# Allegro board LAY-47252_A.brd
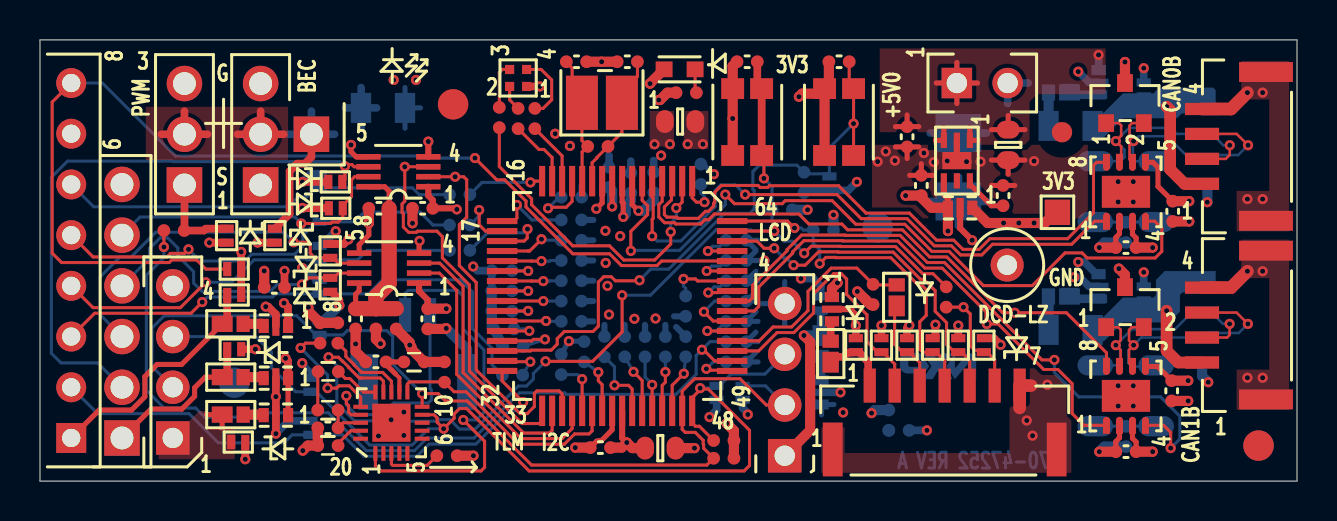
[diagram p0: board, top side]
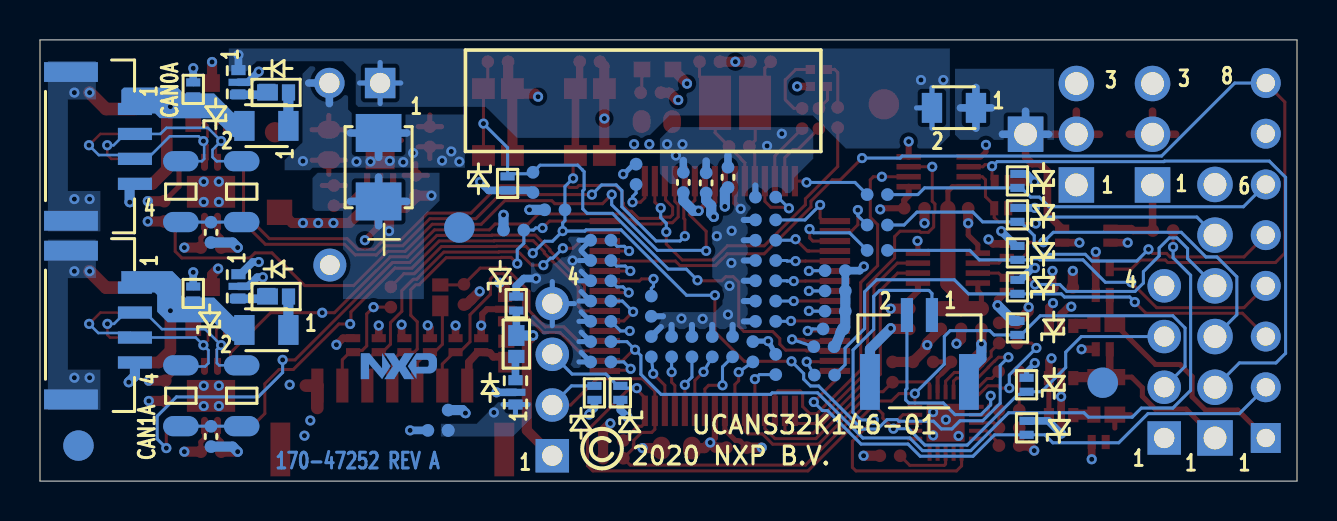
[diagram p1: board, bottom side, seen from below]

Outline 62.87 x 22.1 mm; copper layers: TOP, L2_GND, L3_PWR, BOTTOM. Coordinates in mm from the lower left corner of the outline.
Outline path: 0,22.1 0,0 62.87,0 62.87,22.1 0,22.1

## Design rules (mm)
constraint set DEFAULT: min track width 0.152
net group CAN0_: nets CAN0_H CAN0_L
net group CAN1_: nets CAN1_H CAN1_L
net group POWER: nets N03706 N08433 N08543 N11553 N17733 N16747780 N16805422 N16833767 N16895535 N16899617 N16939568

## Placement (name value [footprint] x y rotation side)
C1  10uF  [CC0603_OV]  32.02 18.01 180 top
C2  10uF  [CC0603_OV]  31.03 1.65 0 top
C3  0.1uF  [CC_FIL_0402]  39.09 4.45 90 bottom
C4  0.1UF  [CC0402_25]  30.7 14.96 90 bottom
C5  0.1UF  [CC0402_25]  29.55 14.94 270 bottom
C6  0.1UF  [CC0402_25]  28.46 15.21 270 bottom
C7  0.1UF  [CC0402_25]  28.03 1.68 180 top
C8  0.1uF  [CC_FIL_0402]  11.8 5.16 180 top
C9  0.1uF  [CC_FIL_0402]  52.95 19.98 270 bottom
C10  0.1uF  [CC_FIL_0402]  11.8 7.77 180 top
C11  0.1UF  [CC0402_25]  11.72 9.7 180 top
C12  4700pF  [CC0402_25]  54.32 2.24 270 bottom
C13  0.1UF  [CC0402_25]  54.32 1.47 180 top
C14  0.1UF  [CC0402_25]  56.6 4.52 270 top
C15  0.1uF  [CC_FIL_0402]  52.95 9.75 270 bottom
C17  0.033UF  [CC0402_25]  16.8 5.97 0 top
C24  0.1UF  [CC0402_25]  54.32 11.7 180 top
C25  0.1UF  [CC0402_25]  56.65 13.51 270 top
C26  4700pF  [CC0402_25]  54.32 12.46 270 bottom
C28  0.1uF  [CC_FIL_0402]  11.8 3.3 180 top
C30  0.033UF  [CC0402_25]  14.4 2.67 180 top
C32  0.1uF  [CC_FIL_0402]  39.61 8.61 270 top
C34  12PF  [CC0402_25]  29.37 21.01 180 top
C35  12PF  [CC0402_25]  26.83 21.01 0 top
C37  0.1UF  [CC0402_25]  19.14 13.67 0 top
C38  0.1UF  [CC0402_25]  16.95 13.67 0 top
C40  0.1UF  [CC0402_25]  43.37 17.25 270 top
C41  0.1UF  [CC0402_25]  44.08 14.81 90 top
C42  0.1UF  [CC0402_25]  39.97 21.01 180 top
C43  0.1uF  [CC_FIL_0402]  46.02 13.69 180 top
C44  0.1UF  [CC0402_25]  35.37 21.01 0 top
C66  0.1UF  [CC0402_25]  15.79 8.13 90 top
C67  0.1UF  [CC0402_25]  19.39 8.13 90 top
C68  470pF  [CC0402_25]  48.17 14.3 90 top
CP1  10uF  [CC0603_OV]  48.42 16.84 270 top
CP2  10uF  [CC3528-21]  45.94 15.72 90 bottom
D1  PMEG2020EPK  [DFN1608D-2]  9.54 3.33 0 top
D2  PESD5V0S1UL  [SOD-882]  9.72 9.32 0 top
D3  PESD5V0S1UL  [SOD-882]  13.98 7.67 90 bottom
D4  PESD5V0S1UL  [SOD-882]  13.53 4.82 90 bottom
D5  PESD5V0S1UL  [SOD-882]  9.92 1.96 0 top
D6  PMEG2020EPK  [DFN1608D-2]  51.07 19.47 180 bottom
D7  PESD5V0S1UL  [SOD-882]  13.53 2.67 90 bottom
D8  PMEG2020EPK  [DFN1608D-2]  51.07 9.25 180 bottom
D9  PESD1CAN  [SOT23_A]  54.27 8.71 0 top
D10  PESD5V0S1UL  [SOD-882]  55.21 19.62 90 bottom
D11  PESD5V0S1UL  [SOD-882]  9.72 6.6 0 top
D12  PESD5V0S1UL  [SOD-882]  14.77 14.99 180 top
D13  PESD5V0S1UL  [SOD-882]  14.52 11.53 90 top
D14  PESD5V0S1UL  [SOD-882]  14.52 9.83 270 top
D15  PESD5V0S1UL  [SOD-882]  14.8 13.67 180 top
D16  PMEG2020EPK  [DFN1608D-2]  9.54 5.21 0 top
D17  PESD5V0S1UL  [SOD-882]  40.8 6.81 90 top
D18  PESD5V0S1UL  [SOD-882]  42.09 6.81 90 top
D19  PESD5V0S1UL  [SOD-882]  43.37 6.81 90 top
D20  PESD5V0S1UL  [SOD-882]  44.65 6.81 90 top
D21  PESD5V0S1UL  [SOD-882]  45.93 6.81 90 top
D22  PESD5V0S1UL  [SOD-882]  47.21 6.81 90 top
D23  PMEG2020EPK  [DFN1608D-2]  42.85 9.2 90 top
D24  PESD5V0S1UL  [SOD-882]  55.21 9.4 90 bottom
D25  PESD5V0S1UL  [SOD-882]  9.33 12.29 270 top
D26  PESD5V0S1UL  [SOD-882]  11.75 12.29 270 top
D28  PESD5V0S1UL  [SOD-882]  13.98 9.73 90 bottom
D29  PMEG2020EPK  [DFN1608D-2]  39.55 6.38 90 top
D30  PESD5V0S1UL  [SOD-882]  13.98 11.43 90 bottom
D31  PESD5V0S1UL  [SOD-882]  13.98 13.34 90 bottom
D32  PESD5V0S1UL  [SOD-882]  13.98 15.04 90 bottom
D33  PESD5V0S1UL  [SOD-882]  9.72 10.62 0 top
D34  PMEG2020EPK  [DFN1608D-2]  39.05 6.87 270 bottom
D35  PMEG2020EPK  [DFN1608D-2]  9.54 7.87 0 top
D36  PESD5V0S1UL  [SOD-882]  39.48 14.91 270 bottom
D37  PESD5V0S1UL  [SOD-882]  35.14 4.42 270 bottom
D38  PESD5V0S1UL  [SOD-882]  33.85 4.42 270 bottom
D43  PESD5V0S1UL  [SOD-882]  39.05 8.89 90 bottom
D47  PESD1CAN  [SOT23_A]  54.27 18.94 0 top
F1  0ZCK0020FF2G  [FUSE_2P2X1P5]  51.55 7.57 0 bottom
F2  0ZCK0020FF2G  [FUSE_2P2X1P5]  51.55 17.79 0 bottom
F3  0ZCK0020FF2G  [FUSE_2P2X1P5]  17.16 18.69 0 bottom
IC1  S32K146  [LQFP64]  28.87 9.27 270 top
IC2  TJA1044GTK/3Z  [SON8_0P65_3P15X3P15]  54.32 4.27 90 top
IC3  SE050C1HQ1/Z01SCZ  [QFN20_0P4_3X3_TAB_1P9]  17.58 2.92 90 top
IC4  TJA1044GTK/3Z  [SON8_0P65_3P15X3P15]  54.32 14.49 90 top
IC5  74LVC2T45DC  [SSOP8_DCU]  17.92 15.49 90 top
IC7  MIC5219-3.3YML  [MLF6_TAB]  45.86 16.05 270 top
IC11  74LVC2T45DC  [SSOP8_DCU]  17.46 10.67 90 top
JP1  HDR 1X2  [HDR102]  45.86 19.94 90 top
L1  120 Ohm  [IND_0402]  18.71 5.97 180 top
L2  120 Ohm  [IND_0402]  14.41 5.49 0 top
L3  120 Ohm  [IND_0402]  14.4 3.56 180 top
L4  120 Ohm  [IND_0402]  14.4 1.78 0 top
LED1  RED/GRN/BLU  [LED4_0P85_1P25SQ_SMT]  23.91 20.19 270 top
LED5  BLUE  [LED_0603]  31.99 20.62 180 top
NOREF  -  []  50.44 9.25 0 top
NOREF#2  -  [unnamed#2]  20.66 18.87 0 top
NOREF#3  -  [unnamed#2]  60.95 1.78 0 top
NOREF#4  -  []  41.52 16.73 90 top
NOREF#5  -  []  10.36 7.45 90 top
NOREF#6  -  []  14.29 6.54 90 top
NOREF#7  -  []  12.06 12.18 90 top
NOREF#8  -  []  14.45 13.67 0 top
NOREF#9  -  []  14.29 12.21 90 top
NOREF#10  -  []  43.06 5.68 90 top
NOREF#11  -  []  51.27 0.48 90 top
NOREF#12  -  []  46.63 14.05 90 top
NOREF#13  -  []  39.24 16.31 90 top
NOREF#14  -  []  41.78 5.68 90 top
NOREF#15  -  []  44.65 6.46 90 top
NOREF#16  -  []  14.29 13.91 0 top
NOREF#17  -  []  61.32 13.04 90 top
NOREF#18  -  []  16.04 3.72 0 top
NOREF#19  -  []  14.29 10.3 90 top
NOREF#20  -  []  9.21 10.31 90 top
NOREF#21  -  []  43.06 5.68 0 top
NOREF#22  -  []  55.52 18.49 0 top
NOREF#23  -  []  15.04 16.01 0 top
NOREF#24  -  []  62.42 12.61 0 top
NOREF#25  -  []  9.21 9.01 0 top
NOREF#26  -  []  58.12 14.89 0 top
NOREF#27  -  []  33.54 4.31 0 top
NOREF#28  -  []  58.12 5.94 90 top
NOREF#29  -  []  8.71 7.45 0 top
NOREF#30  -  []  34.64 16.31 0 top
NOREF#31  -  []  62.87 0 90 top
NOREF#32  -  []  33.85 4.07 90 top
NOREF#33  -  []  39.09 3.84 90 top
NOREF#34  -  []  15.31 12.74 0 top
NOREF#35  -  []  12.41 5.51 90 top
NOREF#36  -  []  39.22 0.48 0 top
NOREF#37  -  []  9.21 6.29 90 top
NOREF#38  -  []  58.12 14.89 90 top
NOREF#39  -  []  45.62 5.68 90 top
NOREF#40  -  []  39.09 3.84 90 top
NOREF#41  -  []  45.93 6.46 90 top
NOREF#42  -  []  45.41 13.69 0 top
NOREF#43  -  []  10.36 4.78 90 top
NOREF#44  -  []  16.41 4.97 0 top
NOREF#45  -  []  13.84 1.54 90 top
NOREF#46  -  []  13.98 11.08 90 top
NOREF#47  -  []  8.71 2.9 0 top
NOREF#48  -  []  58.12 9.69 0 top
NOREF#49  -  []  39.05 8.54 90 top
NOREF#50  -  []  40.8 6.46 90 top
NOREF#51  -  []  39.65 1.58 0 top
NOREF#52  -  []  14.21 10.4 0 top
NOREF#53  -  []  58.12 18.64 0 top
NOREF#54  -  []  15.28 14.06 90 top
NOREF#55  -  []  39.05 6.24 90 top
NOREF#56  -  []  15.31 12.74 90 top
NOREF#57  -  []  22.15 1.4 90 top
NOREF#58  -  []  44.93 8.38 90 top
NOREF#59  -  []  11.19 7.77 0 top
NOREF#60  -  []  13.84 1.54 0 top
NOREF#61  -  []  9.11 7.87 0 top
NOREF#62  -  []  53.54 19.04 90 top
NOREF#63  -  []  14.42 14.99 0 top
NOREF#64  -  []  33.82 13.03 0 top
NOREF#65  -  []  9.21 9.01 90 top
NOREF#66  -  []  61.32 4.09 90 top
NOREF#67  -  []  11.8 5.16 0 top
NOREF#68  -  []  9.37 9.32 0 top
NOREF#69  -  []  41.78 5.68 0 top
NOREF#70  -  []  62.42 20.91 0 top
NOREF#71  -  []  9.57 1.96 0 top
NOREF#72  -  []  9.41 1.65 0 top
NOREF#73  -  []  41.5 4.78 0 top
NOREF#74  -  []  13.53 2.32 90 top
NOREF#75  -  []  14.29 6.54 0 top
NOREF#76  -  []  23.29 20.82 90 top
NOREF#77  -  []  12.41 8.13 90 top
NOREF#78  -  []  9.37 10.62 0 top
NOREF#79  -  []  55.52 8.27 0 top
NOREF#80  -  []  24.34 19.77 90 top
NOREF#81  -  []  39.65 1.58 0 top
NOREF#82  -  []  41.12 7.69 90 top
NOREF#83  -  []  39.61 8 90 top
NOREF#84  -  []  53.3 10.36 90 top
NOREF#85  -  []  58.12 14.89 90 top
NOREF#86  -  []  70.72 11.97 90 top
NOREF#87  -  []  12.06 12.18 0 top
NOREF#88  -  []  33.54 4.31 90 top
NOREF#89  -  []  27.58 3.84 90 top
NOREF#90  -  []  58.12 14.89 90 top
NOREF#91  -  []  52.95 19.37 90 top
NOREF#92  -  [unnamed#2]  51.12 17.48 0 top
NOREF#93  -  []  19.11 2.12 90 top
NOREF#94  -  []  14.83 9.72 0 top
NOREF#95  -  []  34.83 4.31 90 top
NOREF#96  -  []  35.14 4.07 90 top
NOREF#97  -  []  58.12 17.39 90 top
NOREF#98  -  []  41.5 4.78 0 top
NOREF#99  -  []  55.21 9.05 90 top
NOREF#100  -  []  39.36 7.76 0 top
NOREF#101  -  []  9.37 6.6 0 top
NOREF#102  -  []  42.87 6.56 0 top
NOREF#103  -  []  23.49 20.62 0 top
NOREF#104  -  []  11.75 11.94 90 top
NOREF#105  -  []  39.24 19.66 0 top
NOREF#106  -  []  39.26 9.22 90 top
NOREF#107  -  []  -390.36 -259.46 0 top
NOREF#108  -  []  23.81 20.76 0 top
NOREF#109  -  []  53.54 8.82 90 top
NOREF#110  -  []  9.21 6.29 0 top
NOREF#111  -  []  13.98 12.98 90 top
NOREF#112  -  []  38.73 3.84 90 top
NOREF#113  -  []  11.19 5.16 0 top
NOREF#114  -  []  11.19 3.3 0 top
NOREF#115  -  []  11.8 7.77 0 top
NOREF#116  -  []  39.48 14.56 90 top
NOREF#117  -  []  52.95 9.75 90 top
NOREF#118  -  []  46.9 5.68 0 top
NOREF#119  -  []  12.41 3.66 90 top
NOREF#120  -  []  58.12 8.44 90 top
NOREF#121  -  []  40.49 5.68 90 top
NOREF#122  -  []  39.36 7.76 90 top
NOREF#123  -  []  0.42 1.61 0 top
NOREF#124  -  []  9.64 12.18 0 top
NOREF#125  -  []  41.62 5.56 90 top
NOREF#126  -  []  14.29 10.3 0 top
NOREF#127  -  []  17.96 13.3 90 top
NOREF#128  -  []  70.72 12.61 90 top
NOREF#129  -  []  55.21 19.27 90 top
NOREF#130  -  []  58.12 18.64 90 top
NOREF#131  -  []  13.84 3.69 0 top
NOREF#132  -  []  15.28 14.06 0 top
NOREF#133  -  []  14.29 8.6 90 top
NOREF#134  -  []  58.12 5.94 0 top
NOREF#135  -  []  34.83 4.31 0 top
NOREF#136  -  []  70.72 3.67 90 top
NOREF#137  -  []  51.89 19.04 0 top
NOREF#138  -  []  21.78 3.84 0 top
NOREF#139  -  []  58.12 9.69 90 top
NOREF#140  -  []  46.02 13.69 0 top
NOREF#141  -  []  -44.79 -167.89 0 top
NOREF#142  -  []  34.62 5.52 90 top
NOREF#143  -  []  42.85 8.78 90 top
NOREF#144  -  []  9.11 5.21 0 top
NOREF#145  -  []  9.41 1.65 90 top
NOREF#146  -  []  61.32 4.09 90 top
NOREF#147  -  []  13.98 14.69 90 top
NOREF#148  -  []  14.52 11.18 90 top
NOREF#149  -  []  45.62 5.68 0 top
NOREF#150  -  []  -5.55 -35.31 0 top
NOREF#151  -  []  53.3 20.59 90 top
NOREF#152  -  []  0 0 0 top
NOREF#153  -  []  52.95 9.14 90 top
NOREF#154  -  []  39.79 15.42 90 top
NOREF#155  -  []  50.44 19.47 0 top
NOREF#156  -  []  44.34 5.68 90 top
NOREF#157  -  []  52.95 19.98 90 top
NOREF#158  -  []  18.26 8.32 0 top
NOREF#159  -  []  55.52 8.27 90 top
NOREF#160  -  []  39.97 5.56 0 top
NOREF#161  -  []  9.64 12.18 90 top
NOREF#162  -  []  13.53 4.47 90 top
NOREF#163  -  []  44.34 5.68 0 top
NOREF#164  -  []  47.21 6.46 90 top
NOREF#165  -  []  61.32 13.04 90 top
NOREF#166  -  []  43.37 6.46 90 top
NOREF#167  -  []  14.21 10.4 90 top
NOREF#168  -  []  58.12 5.94 90 top
NOREF#169  -  []  61.32 4.09 90 top
NOREF#170  -  []  46.82 5.11 90 top
NOREF#171  -  []  13.98 9.38 90 top
NOREF#172  -  []  11.8 3.3 0 top
NOREF#173  -  []  9.33 11.94 90 top
NOREF#174  -  []  49.75 11.74 0 top
NOREF#175  -  []  -363.69 261.62 0 top
NOREF#176  -  []  42.09 6.46 90 top
NOREF#177  -  []  13.98 7.32 90 top
NOREF#178  -  []  10.36 2.9 90 top
NOREF#179  -  []  43.28 8.38 0 top
NOREF#180  -  []  14.29 12.21 0 top
NOREF#181  -  []  13.84 3.69 90 top
NOREF#182  -  []  14.83 9.72 90 top
NOREF#183  -  []  62.42 11.97 0 top
NOREF#184  -  []  14.29 13.91 90 top
NOREF#185  -  []  33.82 13.03 90 top
NOREF#186  -  []  39.61 8.61 90 top
NOREF#187  -  []  62.42 3.67 0 top
NOREF#188  -  []  70.72 20.91 90 top
NOREF#189  -  []  41.52 16.73 0 top
NOREF#190  -  []  39.55 5.96 90 top
NOREF#191  -  []  51.89 8.82 0 top
NOREF#192  -  []  9.11 3.33 0 top
NOREF#193  -  []  46.9 5.68 90 top
NOREF#194  -  []  58.12 5.94 90 top
NOREF#195  -  []  40.49 5.68 0 top
NOREF#196  -  []  55.52 18.49 90 top
NOREF#197  -  []  23.29 22.07 0 top
NOREF#198  -  []  8.71 4.78 0 top
NOREF#199  -  []  9.21 10.31 0 top
NOREF#200  -  []  14.52 9.48 90 top
NOREF#201  -  []  36.09 16.31 90 top
NOREF#202  -  []  39.17 15.42 0 top
NOREF#203  -  []  39.47 7.69 0 top
NOREF#204  -  []  61.32 13.04 90 top
NOREF#205  -  []  14.29 8.6 0 top
NOREF#206  -  []  50.85 1.58 90 top
NOREF#207  -  []  34.76 1.6 180 bottom
NOREF#208  -  [unnamed#2]  60.95 1.78 180 bottom
NOREF#209  -  []  46.82 5.11 180 bottom
NOREF#210  -  [unnamed#2]  41.9 12.7 180 bottom
NOREF#211  -  [unnamed#2]  9.72 4.93 180 bottom
NOREF#212  -  []  23.81 21.59 0 bottom
P1  HDR 1X8  [HDR1X8_2P54_TH]  1.56 2.16 180 top
P2  HDR_1X6  [HDR106_B]  4.1 2.16 180 top
P3  HDR_1X4  [HDR104]  6.64 2.16 180 top
P4  HDR_1X4  [HDR104]  37.25 1.27 180 top
P5  CON_1X4  [CON_1X4_1P25_8P25X4P25_SM_RA]  60.37 7.82 270 bottom
P6  CON_1X7  [CON1X7_1P25_12X4P05_SM_RA]  45.25 2.53 0 top
P7  CON_1X4  [CON_1X4_1P25_8P25X4P25_SM_RA]  60.37 16.76 90 top
P8  CON_1X4  [CON_1X4_1P25_8P25X4P25_SM_RA]  60.37 16.76 270 bottom
P9  CON_1X4  [CON_1X4_1P25_8P25X4P25_SM_RA]  60.37 7.82 90 top
P10  CON 1X2  [CON_1X2_1P25_5P75X4P25_SM]  18.88 5.99 180 bottom
P11  HDR 1X3  [HDR103_A]  11.04 14.83 180 top
P12  HDR 1X3  [HDR103_A]  7.23 14.83 180 top
P13  HDR_1X1_TH  [HDR101_045T]  13.58 17.37 180 top
R1  49.9  [RC0402_25]  23.63 5.31 180 bottom
R2  49.9  [RC0402_25]  20.99 11.56 180 bottom
R3  60.4  [RC1206_OV]  55.83 14.5 270 bottom
R4  60.4  [RC1206_OV]  52.78 14.5 270 bottom
R5  3.3K  [RC0402_25]  20.36 1.27 180 top
R6  3.3K  [RC0402_25]  14.01 7.42 270 top
R7  49.9  [RC0402_25]  20.99 12.83 180 bottom
R8  10.0K  [RC0402_25]  41.67 9.35 90 top
R9  10.0K  [RC0402_25]  39.18 12.57 180 bottom
R10  1.0K  [RC0402_25]  45.33 9.22 270 top
R11  10.0K  [RC0402_25]  37.12 13.59 180 bottom
R12  49.9  [RC0402_25]  20.99 14.35 180 bottom
R13  1M  [RC0402_25]  27.9 16.76 180 top
R14  100K  [RC0402_25]  23.1 10.54 0 bottom
R15  100K  [RC0402_25]  26.58 10.03 180 bottom
R16  100K  [RC0402_25]  26.58 8 180 bottom
R17  100K  [RC0402_25]  23.2 7.62 0 bottom
R18  6.8K  [RC0402_25]  24.75 18.16 90 top
R19  6.8K  [RC0402_25]  23.91 18.16 90 top
R20  6.8K  [RC0402_25]  22.97 18.21 90 top
R21  100K  [RC0402_25]  23.66 6.73 0 bottom
R22  10.0K  [RC0402_25]  38.21 14.96 270 bottom
R23  60.4  [RC1206_OV]  52.78 4.27 270 bottom
R24  60.4  [RC1206_OV]  55.83 4.27 270 bottom
R25  100K  [RC0402_25]  32.3 8.76 90 bottom
R26  100K  [RC0402_25]  26.07 5.84 270 bottom
R27  3.3K  [RC0402_25]  14.9 7.42 270 top
R28  330  [RC0402_25]  6.71 12.55 0 top
R36  100K  [RC0402_25]  34.82 12.07 180 bottom
R39  3.3K  [RC0402_25]  34.2 2.03 180 top
R40  3.3K  [RC0402_25]  34.2 1.14 180 top
R41  0  [RC0402_25]  42.46 3.05 90 bottom
R42  0  [RC0402_25]  42.96 2.54 180 bottom
R43  3.3K  [RC0402_25]  20.23 5.46 270 top
R44  0  [RC0402_25]  16.8 8.13 90 top
R46  0  [RC0402_25]  17.82 8.13 270 top
R53  100K  [RC0402_25]  33.06 15.37 270 bottom
R55  100K  [RC0402_25]  26.58 14.22 180 bottom
R56  100K  [RC0402_25]  26.58 13.08 180 bottom
R57  100K  [RC0402_25]  26.58 12.07 180 bottom
R58  100K  [RC0402_25]  26.58 11.05 180 bottom
R59  100K  [RC0402_25]  23.1 9.52 0 bottom
R60  100K  [RC0402_25]  26.58 9.02 180 bottom
R61  100K  [RC0402_25]  23.1 8.51 0 bottom
R63  100K  [RC0402_25]  32.3 6.73 270 bottom
R64  100K  [RC0402_25]  31.28 6.73 270 bottom
R65  100K  [RC0402_25]  30.26 6.73 270 bottom
R66  100K  [RC0402_25]  29.25 6.73 270 bottom
R67  100K  [RC0402_25]  28.23 6.73 270 bottom
R68  100K  [RC0402_25]  27.22 6.48 270 bottom
R69  100K  [RC0402_25]  34.82 5.97 180 bottom
R70  100K  [RC0402_25]  34.82 6.98 180 bottom
R71  100K  [RC0402_25]  34.82 8 180 bottom
R72  100K  [RC0402_25]  34.82 9.02 180 bottom
R75  100K  [RC0402_25]  34.82 10.03 180 bottom
R76  100K  [RC0402_25]  34.82 11.05 180 bottom
R80  1.0K  [RC0402_25]  32.32 19.46 180 top
SW1  EVP-AA602W  [SW4_SPST_3P5X2P9_SM]  35.37 17.98 90 top
SW3  EVP-AA602W  [SW4_SPST_3P5X2P9_SM]  39.97 17.98 270 top
TP7  TP 50MILS SQ  [TESTPOINT_050_SQ]  50.89 13.46 0 top
TP8  TERMINAL ASSY  [TP_039_130MIL_TH]  48.37 10.82 0 top
Y1  8MHZ  [XTAL2_3P3X2P6]  28.1 18.95 180 top

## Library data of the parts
C1 C2 C4-C7 C11-C14 C17 C24-C26 C30 C34 C35 C37 C38 C40-C42 C44 C66-C68 CP1 = CAP_NP
C3 C8-C10 C15 C28 C32 C43 = EMIFILTER_NFM21P
CP2 = CAP_POL
D1 D6 D8 D16 D23 D29 D34 D35 = DIODE_SCHTKY
D2-D5 D7 D10-D15 D17-D22 D24-D26 D28 D30-D33 D36-D38 D43 = DIODE_TVS
D9 D47 = DIODE_BIDIR_3P
F1-F3 = FUSE_RESETTABLE
IC1 = S32K146_64P_ALT
IC2 IC4 = TJA1044GT3_HVSON8
IC3 = SE050TBD_HX2QFN20
IC5 IC11 = 74LVC2T45DC
IC7 = MIC5305_MLF_6P
JP1 = CONN_HDR_2X1
L1-L4 = INDUCTOR_FERRITE
LED1 = LED_TRI_SMLP34RGB1W3
LED5 = LED
P1 = CONN_HDR_8X1
P2 = CONN_HDR_6X1
P3 P4 = CONN_HDR_4X1
P5 P7-P9 = CONN_1x4_SHLD
P6 = CONN_1X7_SHLD
P10 = CONN_2X1_SH
P11 P12 = CONN_HDR_3X1
P13 = CONN_HDR_1X1
R1-R28 R36 R39-R44 R46 R53 R55-R61 R63-R72 R75 R76 R80 = RES
SW1 SW3 = SW4_LT_SPST_4P
TP7 = T POINT S
TP8 = TestLoop
Y1 = XTAL

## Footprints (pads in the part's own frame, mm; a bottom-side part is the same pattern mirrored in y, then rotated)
CC0402_25
  round 0.635 smd: 1(-0.508,0) 2(0.508,0)
CC0603_OV
  oval 0.889x1.143 smd: 1(-0.762,0) 2(0.762,0)
CC3528-21
  rect 1.905x2.286 smd: 1(-1.714,0) 2(1.714,0)
CC_FIL_0402
  rect 0.508x0.711 smd: 1(-0.61,0) 3(0.61,0)
  rect 0.356x0.991 smd: 2(0,0)
CON1X7_1P25_12X4P05_SM_RA
  rect 0.61x1.702 smd: 1(-3.75,2.25) 2(-2.5,2.25) 3(-1.25,2.25) 4(0,2.25) 5(1.25,2.25) 6(2.5,2.25) 7(3.75,2.25)
  rect 0.991x2.692 smd: SH1(-5.6,-0.95) SH2(5.6,-0.95)
CON_1X2_1P25_5P75X4P25_SM
  rect 0.61x1.702 smd: 1(0.625,2.322) 2(-0.625,2.322)
  rect 0.991x2.794 smd: S1(-2.475,-1.028) S2(2.475,-1.028)
CON_1X4_1P25_8P25X4P25_SM_RA
  rect 0.61x1.702 smd: 1(-1.875,2.247) 2(-0.625,2.247) 3(0.625,2.247) 4(1.875,2.247)
  rect 0.991x2.692 smd: SH1(-3.725,-0.953) SH2(3.725,-0.953)
DFN1608D-2
  rect 0.66x0.813 smd: A(0.625,0)
  rect 1.041x0.813 smd: C(-0.425,0)
FUSE_2P2X1P5
  rect 1.016x1.499 smd: 1(-1.1,0) 2(1.1,0)
HDR1X8_2P54_TH
  rect 1.499x1.499 hole 0.914: 1(0,0)
  round 1.499 hole 0.914: 2(0,-2.54) 3(0,-5.08) 4(0,-7.62) 5(0,-10.16) 6(0,-12.7) 7(0,-15.24) 8(0,-17.78)
HDR101_045T
  rect 1.778x1.778 hole 1.143: 1(0,0)
HDR102
  rect 1.524x1.524 hole 1.016: 1(0,0)
  round 1.524 hole 1.016: 2(0,-2.54)
HDR103_A
  rect 1.778x1.778 hole 1.143: 1(0,0)
  round 1.778 hole 1.143: 2(0,-2.54) 3(0,-5.08)
HDR104
  rect 1.676x1.676 hole 1.016: 1(0,0)
  round 1.676 hole 1.016: 2(0,-2.54) 3(0,-5.08) 4(0,-7.62)
HDR106_B
  rect 1.778x1.778 hole 1.143: 1(0,0)
  round 1.778 hole 1.143: 2(0,-2.54) 3(0,-5.08) 4(0,-7.62) 5(0,-10.16) 6(0,-12.7)
IND_0402
  round 0.635 smd: 1(-0.508,0) 2(0.508,0)
LED4_0P85_1P25SQ_SMT
  rect 0.457x0.457 smd: 1(0.425,0.425) 2(0.425,-0.425) 3(-0.425,-0.425) 4(-0.425,0.425)
LED_0603
  rect 0.838x0.787 smd: A(-0.775,0) C(0.775,0)
LQFP64
  rect 1.524x0.305 smd: 1(-5.753,3.753) 2(-5.753,3.252) 3(-5.753,2.752) 4(-5.753,2.252) 5(-5.753,1.751) 6(-5.753,1.251) 7(-5.753,0.751) 8(-5.753,0.25) 9(-5.753,-0.25) 10(-5.753,-0.751) 11(-5.753,-1.251) 12(-5.753,-1.751) 13(-5.753,-2.252) 14(-5.753,-2.752) 15(-5.753,-3.252) 16(-5.753,-3.753) 33(5.753,-3.753) 34(5.753,-3.252) 35(5.753,-2.752) 36(5.753,-2.252) 37(5.753,-1.751) 38(5.753,-1.251) 39(5.753,-0.751) 40(5.753,-0.25) 41(5.753,0.25) 42(5.753,0.751) 43(5.753,1.251) 44(5.753,1.751) 45(5.753,2.252) 46(5.753,2.752) 47(5.753,3.252) 48(5.753,3.753)
  rect 0.305x1.524 smd: 17(-3.753,-5.753) 18(-3.252,-5.753) 19(-2.752,-5.753) 20(-2.252,-5.753) 21(-1.751,-5.753) 22(-1.251,-5.753) 23(-0.751,-5.753) 24(-0.25,-5.753) 25(0.25,-5.753) 26(0.751,-5.753) 27(1.251,-5.753) 28(1.751,-5.753) 29(2.252,-5.753) 30(2.752,-5.753) 31(3.252,-5.753) 32(3.753,-5.753) 49(3.753,5.753) 50(3.252,5.753) 51(2.752,5.753) 52(2.252,5.753) 53(1.751,5.753) 54(1.251,5.753) 55(0.751,5.753) 56(0.25,5.753) 57(-0.25,5.753) 58(-0.751,5.753) 59(-1.251,5.753) 60(-1.751,5.753) 61(-2.252,5.753) 62(-2.752,5.753) 63(-3.252,5.753) 64(-3.753,5.753)
MLF6_TAB
  rect 0.762x0.305 smd: 1(-1.016,0.65) 2(-1.016,0) 3(-1.016,-0.65) 4(1.016,-0.65) 5(1.016,0) 6(1.016,0.65)
  rect 0.864x1.448 smd: 7(0,0)
QFN20_0P4_3X3_TAB_1P9
  rect 0.737x0.203 smd: 1(-1.538,0.8) 2(-1.538,0.4) 3(-1.538,0) 4(-1.538,-0.4) 5(-1.538,-0.8) 11(1.538,-0.8) 12(1.538,-0.4) 13(1.538,0) 14(1.538,0.4) 15(1.538,0.8)
  rect 0.203x0.737 smd: 6(-0.8,-1.538) 7(-0.4,-1.538) 8(0,-1.538) 9(0.4,-1.538) 10(0.8,-1.538) 16(0.8,1.538) 17(0.4,1.538) 18(0,1.538) 19(-0.4,1.538) 20(-0.8,1.538)
  rect 1.905x1.905 smd: 21(0,0)
RC0402_25
  round 0.635 smd: 1(-0.508,0) 2(0.508,0)
RC1206_OV
  oval 1.016x1.778 smd: 1(-1.524,0) 2(1.524,0)
SOD-882
  rect 0.406x0.711 smd: A(0.35,0) C(-0.35,0)
SON8_0P65_3P15X3P15
  custom 0.088x0.088 smd: 1(-1.475,0.975) 2(-1.475,0.325) 3(-1.475,-0.325) 4(-1.475,-0.975) 5(1.475,-0.975) 6(1.475,-0.325) 7(1.475,0.325) 8(1.475,0.975)
  rect 1.6x2.413 smd: 9(0,0)
SOT23_A
  rect 0.787x0.889 smd: 1(-0.94,-1.003) 2(0.94,-1.003) 3(0,1.003)
SSOP8_DCU
  rect 0.279x1.219 smd: 1(-0.75,-1.499) 2(-0.25,-1.499) 3(0.25,-1.499) 4(0.75,-1.499) 5(0.75,1.499) 6(0.25,1.499) 7(-0.25,1.499) 8(-0.75,1.499)
SW4_SPST_3P5X2P9_SM
  rect 1.041x1.143 smd: A1(-1.675,0.725) A2(1.675,0.725) B1(-1.675,-0.725) B2(1.675,-0.725)
TESTPOINT_050_SQ
  rect 1.27x1.27 smd: 1(0,0)
TP_039_130MIL_TH
  round 1.651 hole 0.991: 1(0,0)
unnamed#2
  round 1.524 smd: (0,0)
XTAL2_3P3X2P6
  rect 1.6x2.718 smd: 1(-1,0) 2(1,0)

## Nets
3V3: C1.1 C2.1 C4.1 C5.2 C6.2 C7.1 C14.1 C25.1 C32.1 C37.2 C42.2 C43.1 C67.2 IC1.7 IC1.8 IC1.9 IC1.41 IC2.5(VIO) IC4.5(VIO) IC5.1 IC5.5 IC11.1 L1.1 LED1.1 R5.1 R6.1 R8.1 R9.1 R11.1 R27.1 R39.1 R40.1 R42.1 R43.1 R46.2 R80.2 SW3.B1 SW3.B2 TP7.1(TP)
5V: C8.1 C9.1 C10.1 C11.1 C13.1 C15.1 C24.1 C28.1 C40.1 CP1.1 F3.2 IC2.3 IC4.3 IC7.1 IC7.3 JP1.1 R41.2 R44.1
GND: C1.2 C2.2 C3.2 C4.2 C5.1 C6.1 C7.2 C8.2 C9.2 C10.2 C11.2 C12.2 C13.2 C14.2 C15.2 C17.1 C24.2 C25.2 C26.2 C28.2 C30.2 C32.2 C34.2 C35.2 C37.1 C38.1 C40.2 C41.2 C43.2 C44.1 C66.1 C67.1 C68.2 CP1.2 CP2.2 D2.A D3.A D4.A D5.A D7.A D9.3(CC) D10.A D11.A D12.A D13.A D14.A D15.A D17.A D18.A D19.A D20.A D21.A D22.A D24.A D25.A D26.A D28.A D30.A D31.A D32.A D33.A D36.A D37.A D38.A D43.A D47.3(CC) IC1.10 IC1.40(VSS_2) IC2.2 IC2.9 IC3.21 IC4.2 IC4.9 IC5.4 IC7.2 IC7.7 IC11.4 IC11.5 JP1.2 L4.1 LED5.C(CATHODE) P1.7 P2.6 P3.4 P4.4 P5.4 P5.SH1 P5.SH2 P6.7 P6.SH1 P6.SH2 P7.4 P7.SH1 P7.SH2 P8.4 P8.SH1 P8.SH2 P9.4 P9.SH1 P9.SH2 P10.S1 P10.S2 P11.3 P12.3 R14.1 R15.1 R16.1 R17.1 R21.1 R22.2 R25.1 R26.1 R36.1 R53.1 R55.1 R56.1 R57.1 R58.1 R59.1 R60.1 R61.1 R63.1 R64.1 R65.1 R66.1 R67.1 R68.1 R69.1 R70.1 R71.1 R72.1 R75.1 R76.1 SW1.A1 SW1.A2 TP8.1(PIN1)
6-WR-SPI_CS_N: IC1.18 R7.1
6-WR-SPI_INT_N: IC1.16 R12.1
6-WR-SPI_MISO: IC1.31 R1.1
6-WR-SPI_MOSI: IC1.19 R2.1
6-WR-SPI_RDY_N: D33.C IC1.60 P1.8
6-WR-SPI_SCK: D7.C IC1.32 P1.2
CAN0_H: D47.1 IC4.7 P7.2 P8.2 R4.1
CAN0_L: D47.2 IC4.6 P7.3 P8.3 R3.1
CAN0_RX: IC1.6 IC4.4
CAN0_STB: IC1.3 IC4.8
CAN0_TX: IC1.5 IC4.1
CAN1_H: D9.1 IC2.7 P5.2 P9.2 R23.1
CAN1_L: D9.2 IC2.6 P5.3 P9.3 R24.1
CAN1_RX: IC1.56 IC2.4
CAN1_STB: IC1.4 IC2.8
CAN1_TX: IC1.55 IC2.1
CS_N: D31.C P1.5 R7.2
I2C_SCL: D3.C D37.C IC1.47 IC3.10 P3.2 P4.2 R40.2
I2C_SDA: D4.C D38.C IC1.48 IC3.9 P3.3 P4.3 R39.2
INT_N: D32.C P1.6 R12.2
LED1_BLUE: IC1.2 R20.1
LED1_GREEN: IC1.14 R18.1
LED1_RED: IC1.15 R19.1
LPUART0_CTS: IC1.36 IC11.2
LPUART0_RTS: IC1.35 IC5.2
LPUART0_RX: IC1.34 IC11.3
LPUART0_TX: IC1.33 IC5.3
LPUART1_RX: D23.A IC1.52 R8.2
LPUART1_TX: D18.C IC1.51 P6.2
MISO: D28.C P1.3 R1.2
MOSI: D30.C P1.4 R2.2
PTA0: IC1.50 R28.1 R70.2
PTA1: IC1.49 R69.2
PTA7: IC1.37 R26.2
PTA10: IC1.58 R25.2
PTA11: IC1.57 R75.2
PTB6: C35.1 IC1.12 R13.2 Y1.2
PTB7: C34.1 IC1.11 R13.1 Y1.1
PTB12: IC1.43 R66.2
PTB13: IC1.42 R67.2
PTC0: IC1.26 R61.2
PTC1: IC1.25 R60.2
PTC2: IC1.21 R58.2
PTC3: IC1.20 R57.2
PTC5: IC1.61 R36.2
PTC14: C42.1 D36.C IC1.30 R22.1 SW3.A1 SW3.A2
PTC15: IC1.29 R21.2
PTC16: IC1.28 R17.2
PTC17: IC1.27 R16.2
PTD1: IC1.1 R53.2
PTD2: IC1.46 R63.2
PTD3: IC1.45 R64.2
PTD4: IC1.44 R65.2
PTD5: IC1.24 R59.2
PTD6: IC1.23 R15.2
PTD7: IC1.22 R14.2
PTE1: IC1.59 R76.2
PTE2: IC1.54 R72.2
PTE3: IC1.13 R55.2
PTE6: IC1.53 R71.2
PTE7: IC1.39 R68.2
PTE8: IC1.17 R56.2
S32_RST_N: C44.2 IC1.63 IC3.14 R10.1 R11.2 SW1.B1 SW1.B2
S32_SWD_CLK: D21.C IC1.62 P6.5
S32_SWD_DIO: D20.C IC1.64 P6.4 R9.2
SE_ENA: IC1.38 IC3.11 R43.2
SE_LA: IC3.17 P10.2
SE_LB: IC3.1 P10.1
SE_SCL: IC3.16 R6.2
SE_SDA: IC3.3 R5.2
UART0_CTS: D14.C IC11.7 P2.4
UART0_RTS: D15.C IC5.7 P2.5
UART0_RX: D13.C IC11.6 P2.3
UART0_TX: D12.C IC5.6 P2.2
N00466: D19.C D23.C P6.3
N00470: D17.C D29.C P6.1
N00518: D22.C P6.6 R10.2
N02898: D10.C F2.2 P7.1 P8.1
N03706: D24.C F1.2 P5.1 P9.1
N08433: D2.C D35.C P1.1
N08543: C38.2 C66.2 IC5.8(VCCB) IC11.8(VCCB) R44.2 R46.1
N11553: D11.C D16.C P2.1
N16948: D1.C D5.C P3.1
N17733: D34.C D43.C P4.1
N18118: C3.1 R41.1 R42.2
N20024: C41.1 C43.3(OUTPUT) CP2.1 IC7.4(VOUT)
N21801: LED5.A R80.1
N42723: LED1.4(CATHODE3) R18.2
N16747780: C10.3(OUTPUT) D35.A
N16752305: C26.1 R3.2 R4.2
N16762980: C12.1 R23.2 R24.2
N16766876: C32.3(OUTPUT) D29.A
N16781617: LED1.3 R20.2
N16781620: LED1.2 R19.2
N16805422: C8.3(OUTPUT) D16.A
N16833767: C28.3(OUTPUT) D1.A
N16834186: C3.3(OUTPUT) D34.A
N16850472: C17.2 IC3.12 L1.2
N16850531: C30.1 IC3.18 L3.1
N16850565: IC3.15 L2.2
N16850567: L2.1 L3.2
N16850641: IC3.19(VSS) L4.2
N16885160: IC3.13 R27.2
N16895535: D8.A F1.1
N16895554: C15.3(OUTPUT) D8.C
N16899266: C9.3(OUTPUT) D6.C
N16899617: D6.A F2.1
N16901866: D26.C F3.1 P13.1
N16903080: D25.C P12.1 R28.2
N16904839: P11.2 P12.2
N16939568: C68.1 IC7.6

Pads without a net: IC3 2 4 5 6 7 8 20; IC7 5; P11 1

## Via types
v1: diameter 0.508, hole 0.254, TOP to BOTTOM, 226 vias

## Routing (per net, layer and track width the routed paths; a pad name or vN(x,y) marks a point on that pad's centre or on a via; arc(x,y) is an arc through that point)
3V3: length 49
  TOP w0.254: IC2.5 55.89,5.74 C14.1 ; IC1.8 29.12,13.97 29.17,13.92 v1(29.17,13.23) ; C25.1 55.92,14.76 55.92,15.71 55.66,15.97 IC4.5 ; v1(29.93,13.54) 29.62,13.85 IC1.7 ; v1(15.56,16.84) 15.56,16.5 15.81,16.24 IC5.5 ; IC1.9 v1(28.62,13.75)
  TOP w0.305: IC1.41 29.12,2.16 v1(29.35,1.93) ; IC5.1 19.42,14.29 19.65,14.07 C37.2 20.76,13.67 20.82,13.61 v1(20.85,13.61) ; C67.2 19.39,9.08 18.96,9.51 IC11.1
  TOP w0.381: LED1.1 v1(25,19.77)
  TOP w0.508: v1(13.42,8.71) 13.42,8.51 R6.1 R27.1 ; v1(40.88,9.5) 41.26,9.12 41.27,9.1 41.32,9.05 41.34,9.04 41.54,8.84 R8.1 ; R43.1 L1.1 18.57,6.61 18.57,6.73 v1(18.49,6.81) 18.49,6.94 R46.2 ; C2.1 29.63,1.65 v1(29.35,1.93) 29.1,1.68 C7.1 ; v1(20.32,8.64) C67.2 ; v1(34.34,2.89) 34.71,2.52 R39.1 R40.1 ; TP7.1 50.79,13.46 50.25,12.93 v1(49.72,12.93) v1(48.96,12.93) v1(48.2,12.93) 47.39,12.93 C43.1 ; v1(30.95,19.09) 31.01,19.09 31.38,19.46 R80.2 ; SW3.B1 39.46,19.88 C42.2 ; SW3.B1 38.99,19.41 38.11,19.41 v1(37.96,19.25) ; SW3.B1 SW3.B2 ; v1(39.89,9.93) 39.61,9.65 C32.1 ; v1(57.48,14.02) C25.1 ; C14.1 v1(57.43,5.03) ; 20.87,1.27 v1(21.68,1.27)
  BOTTOM w0.381: R42.1 v1(44.36,2.54)
  BOTTOM w0.508: C4.1 30.7,14.05 30.19,13.54 v1(29.93,13.54) ; v1(28.62,13.75) 28.62,14.55 C6.2 ; R9.1 v1(39.69,13.34) ; v1(29.17,13.23) 29.17,13.26 29.3,13.39 29.3,13.8 29.55,14.06 C5.2 ; R11.1 v1(38.39,13.59)
  vias: v1(32.39,16.88) v1(33.16,16.88)
5V: length 30.5
  TOP w0.254: 46.51,17.72 IC7.1 46.93,17.07 ; 45.21,17.72 IC7.3 44.79,17.07 ; CP1.1 48.42,18.31 ; CP1.1 49.26,17.6 ; CP1.1 47.59,17.6 ; 42.79,17.75 C40.1 ; C40.1 43.95,17.75 ; C40.1 43.37,18.34 ; JP1.1 45.86,20.97 ; JP1.1 46.89,19.94 ; JP1.1 44.83,19.94 ; JP1.1 45.86,18.91 ; C28.1 C8.1 ; C24.1 54.83,12.18 54.64,12.36 IC4.3 ; C13.1 54.83,1.96 54.64,2.14 IC2.3
  TOP w0.381: C11.1 v1(12.23,10.53) ; C8.1 12.41,6.02 v1(12.28,6.15) ; C10.1 12.41,8.71 v1(12.2,8.92)
  TOP w0.508: C24.1 v1(55.65,11.7) ; C13.1 v1(55.65,1.47) ; v1(17.03,6.88) 16.8,7.11 R44.1
  BOTTOM w0.254: 45.86,18.91 JP1.1 ; JP1.1 44.83,19.94 ; JP1.1 46.89,19.94 ; JP1.1 45.86,20.97 ; F3.2 19.03,18.69 ; F3.2 18.26,17.68 ; F3.2 18.26,19.71
  BOTTOM w0.381: C9.1 v1(52.95,21.35) ; C15.1 52.84,10.36 52.23,10.97 v1(51.93,10.97)
  BOTTOM w0.508: R41.2 41.74,3.56 v1(41.59,3.4)
  vias: v1(17.69,20.09) v1(18.81,20.09)
GND: length 165.1
  TOP w0.254: v1(18.98,12.03) 18.96,12.01 IC11.4 ; IC1.10 28.12,13.93 v1(27.83,13.64) ; 48.76,14.81 C68.2 47.59,14.81 ; IC1.40 28.62,2.56 28.08,2.03 28,2.03 27.84,2 C7.2 ; 42.79,16.74 C40.2 ; C40.2 43.95,16.74 ; C40.2 43.37,16.15 ; C13.2 53.81,1.98 53.99,2.16 IC2.2 ; 47.59,16.08 CP1.2 ; CP1.2 48.42,15.37 ; CP1.2 49.26,16.08 ; IC4.2 53.99,12.39 53.81,12.2 C24.2 ; IC11.5 15.96,11.84 16.45,12.32 v1(16.45,12.92) ; C41.2 44.67,15.32 ; C41.2 43.5,15.32 ; C41.2 44.08,15.9
  TOP w0.305: IC7.2 IC7.7 ; v1(46.62,12.07) 46.02,12.66 C43.2 ; v1(40.8,7.79) 40.75,7.84 40.75,8.37 40.52,8.61 C32.2 ; v1(19.42,17.01) IC5.4
  TOP w0.381: D21.A v1(45.93,7.79) ; D22.A 47.72,7.16 v1(48.05,6.83) ; D19.A 43.37,7.69 v1(43.48,7.8) ; D11.A v1(10.78,6.6) ; D5.A v1(10.27,1.09) ; v1(44.79,7.83) 44.79,7.3 D20.A ; C8.2 v1(11.8,4.23) C28.2 v1(11.8,2.37) ; v1(13.12,13.69) 13.14,13.67 D15.A ; v1(11.29,8.74) 11.42,8.74 11.8,8.36 C10.2 ; D14.A 14.58,9.48 14.97,9.08 v1(14.97,8.8) ; D26.A v1(10.88,11.94) ; v1(15.43,12.11) 15.21,11.88 D13.A ; D25.A v1(8.47,11.94) ; D18.A v1(42.09,7.79) ; v1(10.07,11.48) D33.A D2.A ; D12.A v1(13.13,14.99) ; v1(40.8,7.79) D17.A
  TOP w0.508: C13.2 v1(52.98,1.47) ; C67.1 20.25,7.62 20.28,7.65 v1(20.32,7.65) ; D47.3 v1(54.27,20.99) ; C11.2 v1(11.21,10.53) ; C38.1 v1(16.45,12.92) ; v1(13.14,1.53) 13.4,1.78 L4.1 C30.2 ; C17.1 16.23,6.03 16.23,6.05 15.79,6.49 v1(15.79,6.87) C66.1 ; C24.2 v1(52.98,11.7) ; D9.3 54.27,10.34 v1(53.96,10.64) ; C34.2 v1(28.09,21.01) C35.2 ; C25.2 v1(57.48,13) ; C37.1 v1(18.63,12.92) ; LED5.C 30.51,19.92 v1(30.51,19.91) ; C2.2 v1(32.74,1.65) ; C44.1 34.64,20.79 SW1.A2 v1(34.64,18.16) SW1.A1 ; C14.2 v1(57.43,4.01) ; v1(26.77,1.68) C7.2
  TOP w0.635: v1(60.39,10.51) 59.57,9.69 P9.4 ; P7.4 59.57,18.64 v1(60.39,19.46) ; 49,3.67 P6.7 49.57,4.78
  L2_GND w0.254: 48.37,9.8 TP8.1 ; TP8.1 47.36,10.82 ; TP8.1 48.37,11.84 ; TP8.1 49.39,10.82 ; 36.22,8.89 P4.4 ; P4.4 37.25,9.92 ; P4.4 37.25,7.86 ; P4.4 38.28,8.89 ; P11.3 12.12,19.91 ; P11.3 11.04,18.83 ; P11.3 11.04,20.99 ; P11.3 9.96,19.91 ; P2.6 4.1,15.94 ; P2.6 5.18,14.86 ; P2.6 4.1,13.78 ; P2.6 3.02,14.86 ; 6.15,19.91 P12.3 ; P12.3 7.23,20.99 ; P12.3 8.31,19.91 ; P12.3 7.23,18.83 ; P3.4 6.64,10.81 ; P3.4 6.64,8.75 ; P3.4 7.67,9.78 ; P3.4 5.61,9.78 ; JP1.2 49.35,19.94 ; JP1.2 48.4,18.99 ; JP1.2 48.4,20.89 ; JP1.2 47.45,19.94 ; P1.7 1.56,18.34 ; P1.7 1.56,16.46 ; P1.7 2.5,17.4
  BOTTOM w0.254: v1(13.12,5.91) 13.53,5.5 D4.A ; 35.92,8 R71.1 35.81,8.48 ; 35.92,10.03 R75.1 35.81,10.51 ; R26.1 26.44,7.01 v1(26.45,7.01) 27.19,7.01 R68.1 ; 37.25,7.79 P4.4 ; P4.4 36.14,8.89 ; P4.4 37.25,9.99 ; 35.92,5.97 R69.1 35.81,6.45 ; 35.81,11.53 R76.1 35.92,11.05 ; 35.92,9.02 R72.1 35.81,9.49 ; 35.92,6.98 R70.1 35.81,7.46 ; 35.92,12.07 R36.1 35.81,11.59 ; v1(33.7,15.37) 33.67,15.37 33.17,15.88 R53.1
  BOTTOM w0.305: R66.1 29.25,7.82 ; 27.09,10.03 27.67,10.03 ; R65.1 30.26,7.82 ; 27.09,14.22 27.09,14.81 ; 27.09,9.02 27.67,9.02 ; R67.1 28.23,7.82 ; 27.09,11.05 27.67,11.05 ; 27.09,13.08 27.67,13.08 ; 31.71,8.25 R25.1 ; 27.09,8 27.67,8 ; 27.09,12.07 27.67,12.07 ; R64.1 31.28,7.82 ; 31.82,7.72 R63.1
  BOTTOM w0.381: D38.A 33.85,3.56 v1(33.49,3.21) ; CP2.2 47.35,17.44 ; CP2.2 45.94,16.22 ; CP2.2 44.53,17.44 ; C6.1 28.46,16.31 ; C9.2 52.46,19.98 v1(51.93,20.51) ; D10.A v1(55.21,20.68) ; C3.2 v1(40.04,4.45) ; C15.2 52.46,9.75 52.01,10.21 v1(51.73,10.21) ; v1(14.79,12.52) 14.06,11.78 D30.A ; v1(40.86,14.99) 40.43,14.56 D36.A 38.32,14.56 R22.2 ; D31.A v1(13.12,13.69) ; D43.A 39.05,9.77 38.67,10.15 v1(38.06,10.15) ; R59.1 R14.1 21.87,10.54 v1(21.67,10.75) ; 48.4,18.91 JP1.2 49.43,19.94 ; v1(35.4,3.34) 35.4,3.4 35.14,3.66 D37.A ; C4.2 30.7,16.05 ; D24.A v1(55.21,10.46) ; v1(13.11,10.68) 13.24,10.68 13.84,10.08 D28.A ; D7.A 12.44,3.02 v1(11.8,2.37) ; C5.1 29.55,16.03 ; D32.A 13.53,15.39 v1(13.13,14.99)
  BOTTOM w0.508: v1(20.32,7.65) 21.36,6.61 P10.S1 ; v1(14.97,8.8) 14.19,8.02 D3.A ; R59.1 22.59,8.51 R61.1 22.6,7.71 R17.1 22.82,7.49 22.82,7.48 22.83,7.41 23.05,6.89 R21.1 ; v1(52.98,1.47) 53.24,1.73 C12.2 ; v1(58.38,13.97) 58.39,13.98 58.39,14.7 58.2,14.89 P8.4 ; C26.2 53.24,11.95 v1(52.98,11.7) ; P5.4 58.12,5.26 v1(58.43,4.95) ; P10.S2 16.41,5.51 15.79,6.13 v1(15.79,6.87)
  vias: v1(16.93,2.26) v1(17.56,3.07) v1(18.2,3.45) v1(18.2,2.29) v1(25.77,17.4) v1(26.5,16.79) v1(28.28,12.54) v1(28.29,10.93) v1(28.38,9.78) v1(28.46,8.34) v1(29.02,12.27) v1(29.73,8.13) v1(30.74,16.87) v1(30.79,8.14) v1(31.07,16.31) v1(31.51,16.88) v1(36.24,11.05) v1(41.9,16) v1(42.3,16.51) v1(42.76,16.05) v1(44.21,16.43) v1(44.7,15.98) v1(45.38,16.04) v1(46.34,16) v1(47.04,16) v1(49.35,3.04) v1(49.64,2.27) v1(49.72,16.03) v1(50.38,4.83) v1(53.93,15) v1(53.93,13.98) v1(53.93,4.78) v1(53.93,3.76) v1(54.68,15) v1(54.68,13.98) v1(54.68,4.78) v1(54.68,3.76) v1(60.39,14.13) v1(60.39,5.18) v1(61.15,19.46) v1(61.15,14.13) v1(61.15,10.51) v1(61.15,5.18)
6-WR-SPI_CS_N: length 3
  TOP w0.152: v1(21.97,13.58) 21.97,12.84 22.28,12.52 IC1.18
  BOTTOM w0.152: v1(21.97,13.58) 21.97,13.29 R7.1
6-WR-SPI_INT_N: length 3.9
  TOP w0.152: v1(24.53,14.96) 24.57,14.96 24.63,15.02 IC1.16
  BOTTOM w0.152: v1(24.53,14.96) 22.11,14.96 R12.1
6-WR-SPI_MISO: length 2.2
  TOP w0.152: v1(24.52,5.98) 23.15,5.98 IC1.31
  BOTTOM w0.152: R1.1 v1(24.52,5.98)
6-WR-SPI_MOSI: length 5.1
  TOP w0.152: IC1.19 24.22,12.02 24.37,12.18 24.37,12.61 v1(24.38,12.62)
  BOTTOM w0.152: R2.1 22.38,12.44 24.18,12.44 24.37,12.62 v1(24.38,12.62)
6-WR-SPI_RDY_N: length 55.2
  TOP w0.152: P1.8 0.61,18.99 0.61,11.42 1.08,10.95 6.46,10.95 6.59,11.07 7.84,11.07 8.29,10.62 D33.C ; IC1.60 31.09,11.02 30.86,10.79 29.08,10.79 28.49,11.38 26.65,11.38 24.31,13.73 24.31,14.02 23.24,15.09 22.85,15.09 v1(21.75,16.18)
  BOTTOM w0.152: P1.8 3.12,19.94 6.77,16.28 19.75,16.28 19.85,16.18 v1(21.75,16.18)
6-WR-SPI_SCK: length 27.5
  TOP w0.152: IC1.32 23.11,5.02 v1(24.17,3.96)
  BOTTOM w0.152: P1.2 2.88,3.38 7.45,3.38 8.92,1.92 12.21,1.92 12.61,2.32 D7.C 15.13,2.32 16.2,1.24 18.85,1.24 19.46,1.85 21.81,1.85 23.48,3.53 23.74,3.53 v1(24.17,3.96)
CAN0_H: length 13.7
  TOP w0.127: P7.2 59.31,16.14 59.51,16.34 v1(59.51,16.82) ; D47.1 53.96,17.93 54.08,17.82 54.08,17.3 v1(53.81,17.03) 54.08,16.76 54.08,16.05 IC4.7
  BOTTOM w0.127: R4.1 54.04,16.02 54.24,16.23 54.24,16.6 v1(53.81,17.03) 54.47,17.69 56.55,17.69 56.85,17.39 P8.2 58.62,17.39 59.19,16.82 v1(59.51,16.82)
CAN0_L: length 14.1
  TOP w0.127: IC4.6 54.5,16.11 54.5,16.83 v1(54.7,17.03) 54.5,17.23 54.5,17.81 54.62,17.93 D47.2 ; P7.3 59.86,17.39 v1(60.42,16.82)
  BOTTOM w0.127: R3.1 54.77,16.02 54.66,16.14 54.66,16.99 v1(54.7,17.03) 54.94,17.27 56.38,17.27 57.51,16.14 P8.3 58.32,16.33 59.93,16.33 v1(60.42,16.82)
CAN0_RX: length 37
  TOP w0.152: IC4.4 55.75,13.02 56.11,12.66 56.11,11.51 55.78,11.18 52.37,11.18 52.12,11.43 51.27,11.43 49.63,9.79 47.18,9.79 45.47,11.51 44.61,11.51 43.25,12.87 40.8,12.87 39.62,14.05 37.27,14.05 37.12,13.89 34.73,13.89 v1(34.28,14.35) ; v1(29.55,11.53) 29.55,12.51 30.39,13.35 30.39,13.79 30.12,14.07 IC1.6
  BOTTOM w0.152: v1(34.28,14.35) 34.28,13.84 31.99,11.56 29.58,11.56 v1(29.55,11.53)
CAN0_STB: length 29.7
  TOP w0.152: IC4.8 52.84,15.97 52.69,15.81 52.69,13.44 51.4,12.14 47.51,12.14 46.98,11.61 46.16,11.61 45.7,12.07 44.84,12.07 43.48,13.42 41.31,13.42 39.94,14.8 36.49,14.8 36.4,14.71 36.02,14.71 35.92,14.81 34.09,14.81 33.74,14.46 33.74,13.97 33.69,13.92 33.69,13.78 33.43,13.51 33.29,13.51 32.93,13.16 31.92,13.16 31.85,13.22 31.36,13.22 31.23,13.35 31.23,13.73 31.58,14.08 31.58,14.99 IC1.3
CAN0_TX: length 29.4
  TOP w0.152: v1(35.27,14.35) 39.87,14.35 41.07,13.14 43.37,13.14 44.73,11.79 45.59,11.79 46.04,11.33 47.1,11.33 47.64,11.86 51.6,11.86 52.75,13.02 IC4.1 ; IC1.5 30.62,14.23 30.67,14.17 30.67,13.16 30.62,13.1 v1(30.62,12.27)
  BOTTOM w0.152: v1(30.62,12.27) 30.86,12.03 32.05,12.03 33.77,13.74 33.77,14.55 34.05,14.83 34.79,14.83 v1(35.27,14.35)
CAN1_H: length 13.7
  TOP w0.127: IC2.7 54.05,5.8 54.05,6.57 v1(53.81,6.81) 54.05,7.05 54.05,7.58 53.92,7.71 D9.1 ; P9.2 59.37,7.19 59.5,7.32 v1(59.5,7.87)
  BOTTOM w0.127: R23.1 53.91,5.8 54.03,5.91 54.03,6.59 v1(53.81,6.81) 54.61,7.61 56.77,7.61 57.6,8.44 P5.2 58.6,8.44 59.17,7.87 v1(59.5,7.87)
CAN1_L: length 14
  TOP w0.127: v1(60.41,7.87) 59.85,8.44 P9.3 ; IC2.6 54.47,5.91 54.47,6.58 v1(54.7,6.81) 54.47,7.04 54.47,7.57 54.61,7.71 D9.2
  BOTTOM w0.127: R24.1 55.77,5.74 54.61,5.74 54.44,5.9 54.44,6.55 v1(54.7,6.81) 55.08,7.19 P5.3 58.35,7.42 59.96,7.42 v1(60.41,7.87)
CAN1_RX: length 32.3
  TOP w0.152: IC2.4 56.2,2.79 56.55,2.44 v1(56.55,1.65) ; v1(50.74,6.07) 50.12,6.07 45.24,10.95 44.38,10.95 43.02,12.31 40.28,12.31 40.27,12.32 38.09,12.32 37.37,11.6 37.37,11.54 35.64,9.8 35.64,9.17 35.48,9.02 IC1.56
  BOTTOM w0.152: v1(50.74,6.07) 50.74,5.44 51.96,4.22 56.04,4.22 57.01,3.25 57.01,2.11 v1(56.55,1.65)
CAN1_STB: length 28.2
  TOP w0.152: IC2.8 53.34,6.43 51.34,8.43 v1(48.76,8.43) 48.15,8.43 45.35,11.23 44.5,11.23 43.14,12.59 40.4,12.59 40.1,12.88 38.46,12.88 37.95,13.38 33.73,13.38 33.44,13.09 33.26,13.09 33.05,12.88 31.8,12.88 31.74,12.94 31.24,12.94 30.95,13.23 30.95,13.84 31.12,14.01 IC1.4
CAN1_TX: length 25.8
  TOP w0.152: IC1.55 35.72,8.52 35.95,8.74 35.95,9.72 37.65,11.42 37.65,11.48 38.21,12.04 40.15,12.04 40.17,12.03 42.91,12.03 44.26,10.67 45.12,10.67 47.32,8.47 47.32,7.91 v1(47.36,7.87) 47.92,7.87 50.2,5.59 50.91,5.59 51.63,4.88 51.63,3.38 52.21,2.79 IC2.1
CS_N: length 21.4
  TOP w0.152: P1.5 2.65,11.23 6.35,11.23 6.52,11.4 7.23,11.4 v1(7.43,11.61)
  BOTTOM w0.152: v1(7.43,11.61) 8.01,11.02 10.25,11.02 10.59,11.36 12.73,11.36 13.14,11.77 13.14,12.29 13.84,12.98 D31.C 15.72,12.98 16.21,13.47 19.01,13.47 19.65,12.83 R7.2
I2C_SCL: length 49.4
  TOP w0.152: P4.2 36.33,3.81 35.01,5.13 32.74,5.13 32.12,4.51 IC1.47 32.12,2.59 32.27,2.44 32.77,2.44 33.17,2.04 33.17,1.86 33.19,1.84 33.19,1.64 R40.2 33.35,0.8 24.58,0.8 21.48,3.91 21.47,3.91 21.37,4.01 20.28,4.01 19.91,4.38 v1(19.11,4.38) IC3.10
  BOTTOM w0.152: P4.2 36.29,4.77 D37.C ; P3.2 5.6,5.74 5.6,7.67 6.21,8.28 12.84,8.28 13.8,7.32 D3.C 15.15,7.32 15.37,7.54 17.35,7.54 17.64,7.25 17.64,5.86 v1(19.11,4.38)
I2C_SDA: length 48.7
  TOP w0.152: 33.69,2.03 32.98,2.75 32.78,2.75 32.62,2.91 IC1.48 32.62,4.18 33.02,4.58 v1(33.02,4.66) 33.07,4.61 33.42,4.61 35.49,2.55 35.49,0.78 35.22,0.51 24.46,0.51 21.34,3.63 20.98,3.63 20.71,3.36 20.71,3.15 v1(20.19,2.62) 19.86,2.95 19.86,3.17 19.71,3.32 IC3.9
  BOTTOM w0.152: v1(20.19,2.62) 19.44,2.62 18.62,1.8 16.49,1.8 13.95,4.34 13.66,4.34 D4.C 12.79,4.47 11.57,5.69 11.57,6.46 10.79,7.24 P3.3 ; P4.3 36.26,5.36 34.56,5.36 33.97,4.77 D38.C 33.73,4.66 33.35,4.66 v1(33.02,4.66)
INT_N: length 19.9
  BOTTOM w0.152: P1.6 2.68,13.74 12.4,13.74 12.89,14.22 13.32,14.22 13.78,14.69 D32.C 18.63,14.69 18.96,14.35 R12.2
LED1_BLUE: length 16.4
  TOP w0.152: v1(31.83,13.68) 32.12,13.97 IC1.2 ; v1(31.55,12.48) 31.55,11.87 30.75,11.07 29.2,11.07 28.49,11.79 26.65,11.79 24.59,13.84 24.59,14.14 22.97,15.75 R20.1
  BOTTOM w0.152: v1(31.55,12.48) 31.55,12.92 31.83,13.2 v1(31.83,13.68)
LED1_GREEN: length 3.2
  TOP w0.152: R18.1 26.11,16.29 IC1.14
LED1_RED: length 3.5
  TOP w0.152: IC1.15 25.61,16.21 25.21,16.61 24.96,16.61 R19.1
LPUART0_CTS: length 14.6
  TOP w0.152: IC11.2 19.98,10.42 20.84,9.55 20.84,5.35 24.06,2.13 26.11,2.13 26.62,2.63 IC1.36
LPUART0_RTS: length 19
  TOP w0.152: IC1.35 26.11,4.36 25.96,4.52 24.85,4.52 24.73,4.39 24.73,3.73 24.37,3.38 24.01,3.38 21.82,5.57 21.82,9.95 20.98,10.79 20.98,12.85 21.34,13.22 21.34,15.09 21.19,15.24 v1(20.76,15.24) IC5.2
LPUART0_RX: length 13.7
  TOP w0.152: IC11.3 19.99,10.92 21.16,9.75 21.16,5.44 24.19,2.41 25.48,2.41 25.61,2.54 IC1.34
LPUART0_TX: length 19
  TOP w0.152: IC1.33 25.11,3.04 24.96,2.88 24.11,2.88 21.48,5.51 21.48,9.83 20.13,11.18 20.13,12.25 19.85,12.52 18.88,12.52 18.82,12.46 18.44,12.46 18.17,12.73 18.17,13.39 18.11,13.45 18.11,13.88 18.24,14.02 v1(18.24,15.74) IC5.3
LPUART1_RX: length 10.7
  TOP w0.152: D23.A 41.7,9.83 R8.2 40.86,10.67 39.58,10.67 38.41,9.51 38.41,8.54 37.59,7.72 36.67,7.72 35.97,7.02 IC1.52
LPUART1_TX: length 14.5
  TOP w0.152: P6.2 42.75,5.86 42.15,6.46 D18.C 41.88,6.46 41.36,6.98 41.36,8.33 40.35,9.35 40.35,10.12 40.08,10.39 39.7,10.39 38.69,9.38 38.69,8.42 37.71,7.44 36.87,7.44 35.94,6.52 IC1.51
MISO: length 26.3
  TOP w0.152: v1(8.12,8.97) 7.56,8.41 2.73,8.41 P1.3
  BOTTOM w0.152: R1.2 22.61,5.83 22.61,6.66 21.63,7.63 21.63,9.48 21.02,10.08 17.14,10.08 16.43,9.38 D28.C 11.79,9.38 11.63,9.22 8.37,9.22 v1(8.12,8.97)
MOSI: length 20.6
  TOP w0.152: v1(8.29,9.96) 7.02,8.69 2.65,8.69 P1.4
  BOTTOM w0.152: R2.2 18.45,11.56 18.45,11.56 16.36,11.56 15.89,11.08 D30.C 13.35,11.08 13.3,11.13 12.92,11.13 12.87,11.08 10.71,11.08 9.58,9.96 v1(8.29,9.96)
PTA0: length 43.4
  TOP w0.152: v1(33.11,6.58) 33.18,6.58 33.74,6.02 IC1.50 ; R28.1 v1(6.2,11.72)
  BOTTOM w0.152: R70.2 33.52,6.98 v1(33.11,6.58) 32.82,6.29 32.82,5.35 31.81,4.34 26.33,4.34 26.25,4.42 23.98,4.42 23.37,3.81 23.37,3.81 21.72,2.16 19.37,2.16 18.73,1.52 16.32,1.52 14.42,3.42 10.65,3.42 10.43,3.2 8.24,3.2 7.78,3.66 6.21,3.66 5.32,4.55 5.32,10.31 6.2,11.19 v1(6.2,11.72)
PTA1: length 2.5
  TOP w0.152: IC1.49 33.97,5.52 33.94,5.55 33.54,5.55 33.47,5.62 33.33,5.62 v1(33.33,5.62)
  BOTTOM w0.152: R69.2 33.67,5.97 v1(33.33,5.62)
PTA7: length 2.7
  TOP w0.152: v1(27.12,5.11) IC1.37
  BOTTOM w0.152: R26.2 26.89,5.33 v1(27.12,5.11)
PTA10: length 3.4
  TOP w0.152: v1(32.19,10.13) 32.79,10.13 32.89,10.02 IC1.58
  BOTTOM w0.152: v1(32.19,10.13) 32.19,9.76 32.3,9.65 R25.2
PTA11: length 2.4
  TOP w0.152: v1(33.43,9.44) 33.87,9.44 33.95,9.52 IC1.57
  BOTTOM w0.152: v1(33.43,9.44) 33.71,9.73 34.01,9.73 R75.2
PTB6: length 6.5
  TOP w0.152: C35.1 26.62,20.68 26.62,19.41 Y1.2 27.1,17.05 R13.2 27.12,16.49 IC1.12
PTB7: length 6.9
  TOP w0.152: C34.1 29.88,20.27 29.1,19.49 Y1.1 29.1,17.46 R13.1 27.85,16.21 27.85,16.18 27.62,15.94 IC1.11
PTB12: length 3
  TOP w0.152: IC1.43 30.12,5.04 v1(29.68,5.47)
  BOTTOM w0.152: R66.2 v1(29.68,5.47)
PTB13: length 3.7
  TOP w0.152: IC1.42 29.62,4.61 29.43,4.8 v1(28.73,4.8)
  BOTTOM w0.152: R67.2 28.73,5.72 v1(28.73,4.8)
PTC0: length 2.1
  TOP w0.152: IC1.26 24.41,8.52 24.41,8.52 v1(24.42,8.52)
  BOTTOM w0.152: v1(24.42,8.52) 24.4,8.51 R61.2
PTC1: length 3
  TOP w0.152: v1(25.17,9.02) 25.17,9.02 IC1.25
  BOTTOM w0.152: R60.2 26.07,9.02 v1(25.17,9.02)
PTC2: length 3
  TOP w0.152: v1(25.08,11.02) 24.59,11.02 24.59,11.02 IC1.21
  BOTTOM w0.152: v1(25.08,11.02) 25.5,11.02 25.53,11.05 R58.2
PTC3: length 3.2
  TOP w0.152: v1(25.08,12.12) 24.49,11.53 24.41,11.53 24.41,11.52 IC1.20
  BOTTOM w0.152: R57.2 25.13,12.07 v1(25.08,12.12)
PTC5: length 2.3
  TOP w0.152: IC1.61 v1(33.41,11.52)
  BOTTOM w0.152: R36.2 34.01,11.76 33.65,11.76 v1(33.41,11.52)
PTC14: length 31.2
  TOP w0.152: IC1.30 24.53,6.52 24.57,6.56 25.57,6.56 25.87,6.86 25.87,7.14 26.23,7.49 27.66,7.49 27.93,7.76 27.93,9.97 28.19,10.24 28.57,10.24 28.78,10.03 29.96,10.03 v1(29.98,10.06) ; SW3.A2 v1(40.69,17.91) SW3.A1 40.47,19.88 C42.1
  BOTTOM w0.152: v1(29.98,10.06) 30.54,10.62 31.45,10.62 34.24,13.41 35.5,13.41 35.72,13.63 35.72,14.54 35.66,14.61 35.66,15.5 35.98,15.82 37.86,15.82 R22.1 38.29,15.39 39.35,15.39 D36.C 39.48,16.7 v1(40.69,17.91)
PTC15: length 3.3
  TOP w0.152: v1(25.26,7.1) 24.67,7.1 24.59,7.02 IC1.29
  BOTTOM w0.152: R21.2 v1(25.26,7.1)
PTC16: length 2.2
  TOP w0.152: v1(24.47,7.52) 24.41,7.52 24.41,7.52 IC1.28
  BOTTOM w0.152: R17.2 24.23,7.62 24.32,7.52 v1(24.47,7.52)
PTC17: length 3
  TOP w0.152: v1(25.31,8.02) IC1.27
  BOTTOM w0.152: v1(25.31,8.02) 25.33,8 R16.2
PTD1: length 2.5
  TOP w0.152: IC1.1 32.62,14.19 32.84,13.97 v1(33.24,13.97)
  BOTTOM w0.152: v1(33.24,13.97) 33.24,14.25 33.06,14.43 R53.2
PTD2: length 3
  TOP w0.152: v1(32.2,5.38) 31.62,4.8 IC1.46
  BOTTOM w0.152: R63.2 v1(32.2,5.38)
PTD3: length 2.8
  TOP w0.152: v1(31.28,5.46) 31.28,4.95 31.12,4.79 IC1.45
  BOTTOM w0.152: R64.2 v1(31.28,5.46)
PTD4: length 2.9
  TOP w0.152: IC1.44 v1(30.62,4.82)
  BOTTOM w0.152: v1(30.62,4.82) 30.62,4.86 30.26,5.21 R65.2
PTD5: length 2.1
  TOP w0.152: IC1.24 24.41,9.52 24.41,9.52 v1(24.42,9.52)
  BOTTOM w0.152: R59.2 24.41,9.52 v1(24.42,9.52)
PTD6: length 3
  TOP w0.152: IC1.23 24.59,10.02 24.59,10.02 v1(25.17,10.02)
  BOTTOM w0.152: v1(25.17,10.02) 25.5,10.02 25.52,10.03 R15.2
PTD7: length 2.1
  TOP w0.152: IC1.22 24.41,10.52 24.41,10.53 v1(24.42,10.53)
  BOTTOM w0.152: R14.2 24.4,10.54 v1(24.42,10.53)
PTE1: length 2.5
  TOP w0.152: v1(33.35,10.52) IC1.59
  BOTTOM w0.152: v1(33.35,10.52) 33.6,10.77 34.04,10.77 R76.2
PTE2: length 2.9
  TOP w0.152: IC1.54 33.67,8.02 v1(33.21,8.48)
  BOTTOM w0.152: R72.2 33.74,9.02 v1(33.21,8.48)
PTE3: length 3.2
  TOP w0.152: IC1.13 26.62,14.01 26.32,13.72 25.46,13.72 v1(25.41,13.67)
  BOTTOM w0.152: v1(25.41,13.67) 25.97,14.22 R55.2
PTE6: length 2.4
  TOP w0.152: IC1.53 v1(33.38,7.52)
  BOTTOM w0.152: R71.2 33.83,7.52 v1(33.38,7.52)
PTE7: length 2.9
  TOP w0.152: v1(27.93,5.46) 27.93,5.45 27.93,5.02 28.12,4.83 IC1.39
  BOTTOM w0.152: R68.2 v1(27.93,5.46)
PTE8: length 4
  TOP w0.152: IC1.17 23.7,13.02 23.85,13.18 v1(23.85,13.83)
  BOTTOM w0.152: R56.2 24.6,13.08 v1(23.85,13.83)
S32_RST_N: length 55.5
  TOP w0.152: IC1.63 v1(36.73,12.52) ; v1(38.23,11.41) 38.58,11.76 40.03,11.76 40.05,11.75 42.79,11.75 44.15,10.39 44.67,10.39 R10.1 ; v1(36.21,15.16) 36.21,16.19 SW1.B1 ; v1(14.43,6.2) 14.93,6.2 15.12,6.01 15.14,6.01 15.44,5.7 15.44,5.69 15.96,5.17 16.07,5.17 16.08,5.16 17.02,5.16 17.18,5.01 IC3.14 ; v1(25.29,6) 27.64,6 29.12,7.47 v1(29.12,9.31)
  TOP w0.381: SW1.B1 SW1.B2 35.88,19.88 C44.2
  BOTTOM w0.152: v1(14.43,6.2) 14.85,5.79 14.85,3.9 15.72,3.02 16.85,3.02 17.26,2.62 17.79,2.62 18.17,3 19.92,3 20,3.08 20.51,3.08 20.98,2.6 21.77,2.6 23.25,4.09 23.25,4.09 23.93,4.76 24.33,4.76 24.68,5.11 24.68,5.39 v1(25.29,6) ; v1(29.12,9.31) 30.53,9.31 33.81,12.59 35.56,12.59 35.62,12.52 v1(36.73,12.52) ; v1(38.23,11.41) 37.63,12.01 37.24,12.01 v1(36.73,12.52) ; v1(36.73,12.52) 36.73,12.93 36.61,13.05 R11.2 36.61,14.76 v1(36.21,15.16)
S32_SWD_CLK: length 17.4
  TOP w0.152: v1(36.72,11.66) 36.22,11.66 35.85,12.02 IC1.62 ; v1(37.69,10.82) 38.27,10.82 38.94,11.48 39.92,11.48 39.93,11.47 42.67,11.47 44.03,10.11 44.2,10.11 44.77,9.54 44.77,8.5 45.34,7.93 45.34,6.86 45.74,6.46 D21.C 46.12,6.46 46.5,6.02 P6.5
  BOTTOM w0.152: v1(36.72,11.66) 37.22,11.17 37.34,11.17 v1(37.69,10.82)
S32_SWD_DIO: length 18
  TOP w0.152: IC1.64 37.39,13.02 v1(37.74,12.68) ; P6.4 45.25,6.03 44.82,6.46 D20.C 44.16,6.46 44,6.61 44,7.98 44.33,8.3 44.33,9.59 44.09,9.83 43.92,9.83 42.56,11.19 39.82,11.19 39.8,11.2 39.31,11.2 v1(39,10.89)
  BOTTOM w0.152: v1(37.74,12.68) 38.08,12.68 38.18,12.57 R9.2 38.67,11.91 39,11.58 v1(39,10.89)
SE_ENA: length 12.3
  TOP w0.152: IC3.11 18.38,4.86 18.48,4.97 20.21,4.97 R43.2 20.71,4.48 21.31,4.48 23.94,1.85 26.23,1.85 26.74,2.36 27.46,2.36 27.62,2.51 IC1.38
SE_LA: length 11
  TOP w0.152: IC3.17 15.56,3.32 15.44,3.45 15.44,3.78 15.32,3.89 v1(15.32,4.27)
  BOTTOM w0.152: v1(15.32,4.27) 15.32,3.81 15.81,3.33 17.11,3.33 17.69,3.91 19.42,3.91 19.57,4.06 19.57,4.57 19.51,4.63 P10.2
SE_LB: length 20.7
  TOP w0.152: v1(21.17,3.06) 22.24,1.99 22.24,0.69 22.06,0.51 17.03,0.51 16.78,0.76 IC3.1
  BOTTOM w0.152: P10.1 18.26,9.4 18.41,9.55 20.88,9.55 21.17,9.25 21.17,7.6 22.21,6.57 22.21,3.44 21.83,3.06 v1(21.17,3.06)
SE_SCL: length 6.1
  TOP w0.152: v1(13.04,6.67) 13.28,6.91 R6.2 ; v1(14.39,4.66) 14.84,4.66 14.96,4.77 15.47,4.77 16.04,4.2 IC3.16
  BOTTOM w0.152: v1(14.39,4.66) 14.39,5.31 v1(13.04,6.67)
SE_SDA: length 3
  TOP w0.152: IC3.3 17.58,0.85 17.64,0.79 19.37,0.79 R5.2
UART0_CTS: length 15.2
  TOP w0.152: IC11.7 14.92,10.42 14.69,10.18 D14.C 13.43,10.18 v1(13.1,9.85)
  BOTTOM w0.152: P2.4 5.47,11.15 5.47,11.65 6.01,12.18 6.39,12.18 6.9,11.67 6.9,11.28 7.68,10.49 7.68,9.92 8.1,9.5 11.52,9.5 11.86,9.85 v1(13.1,9.85)
UART0_RTS: length 14.7
  TOP w0.152: v1(13.07,12.9) 14.53,12.9 14.6,12.97 14.92,12.97 15.15,13.2 D15.C 15.15,13.81 15.58,14.25 15.58,15.09 15.74,15.24 IC5.7
  BOTTOM w0.152: v1(13.07,12.9) 12.74,13.23 5.01,13.23 P2.5
UART0_RX: length 18.2
  TOP w0.152: v1(12.69,11.96) 13.36,11.96 13.52,11.81 13.52,11.42 13.75,11.18 D13.C 14.64,11.18 14.91,10.92 IC11.6
  BOTTOM w0.152: P2.3 3.01,8.33 3.01,10.23 4.01,11.23 4.55,11.23 5.79,12.46 12.19,12.46 v1(12.69,11.96)
UART0_TX: length 30.3
  TOP w0.152: IC5.6 15.71,15.74 15.61,15.85 15.35,15.85 15.28,15.77 v1(15.25,15.77) 15.25,15.12 D12.C
  BOTTOM w0.152: v1(15.25,15.77) 15.23,15.77 15,16 6.66,16 6.63,16.03 1.38,16.03 0.57,15.22 0.57,6.4 1.05,5.92 2.88,5.92 P2.2
N00466: length 4.8
  TOP w0.152: P6.3 44,5.94 43.48,6.46 D19.C 43.14,6.46 42.75,6.85 42.75,8.67 D23.C
N00470: length 3.5
  TOP w0.381: D29.C 39.82,6.22 40.2,6.22 40.37,6.42 D17.C 40.98,6.45 41.42,5.96 41.42,4.86 P6.1
N00518: length 5.7
  TOP w0.152: R10.2 v1(46.19,8.71) 46.53,8.37 46.53,6.77 46.75,6.54 47.12,6.54 D22.C 47.37,6.46 47.75,6.08 P6.6
N02898: length 5.1
  TOP w0.584: P7.1 57.25,14.89 56.53,15.61 56.53,18.58 v1(56.35,18.76)
N03706: length 4
  TOP w0.584: v1(56.35,8.53) 56.35,6.52 56.93,5.94 P9.1
N08433: length 12.1
  TOP w0.254: P1.1 2.96,3.56 4.58,3.56 5.24,4.23 5.24,5.23 5.85,5.84 7.08,5.84 D35.C
  TOP w0.381: D2.C 9.37,8.13 D35.C
N08543: length 10.7
  TOP w0.254: IC5.8 17.24,14.74 17.46,14.52 C38.2 ; IC11.8 15.96,9.53 15.79,9.35 C66.2
  TOP w0.762: R44.2 C66.2 ; R44.2 R46.1 ; R44.2 16.8,9.24 17.46,9.9 C38.2
N11553: length 8
  TOP w0.254: D16.C 8.27,5.21 7.73,4.67 7.73,4.25 7.09,3.61 5.55,3.61 P2.1
  TOP w0.381: D16.C 9.37,5.46 D11.C
N16948: length 1.5
  TOP w0.254: 8.33,3.33 D1.C 9.11,2.65
N17733: length 8.8
  TOP w0.508: v1(38.21,7.29) 38.52,6.98 38.52,2.54 P4.1
  BOTTOM w0.381: D43.C 39.05,8.53 D34.C
  BOTTOM w0.508: v1(38.21,7.29) D34.C
N18118: length 1.8
  BOTTOM w0.254: 38.47,3.84 C3.1 ; C3.1 39.09,3.31 ; C3.1 39.71,3.84
  vias: v1(40.17,3.44)
N20024: length 10.3
  TOP w0.305: IC7.4 45.21,14.37 45.41,14.16 C43.3
  TOP w0.508: v1(43.29,14.3) C41.1 44.08,14.2 44.59,13.69 C43.3 v1(45.41,12.52)
  BOTTOM w0.381: CP2.1 45.94,15.23 ; CP2.1 45.94,12.79 ; CP2.1 44.53,14.01 ; CP2.1 47.35,14.01
N21801: length 1.2
  TOP w0.152: R80.1 32.77,19.52 LED5.A
N42723: length 3.5
  TOP w0.152: R18.2 25.16,18.67 25.59,19.1 25.59,20.09 25.07,20.62 LED1.4
